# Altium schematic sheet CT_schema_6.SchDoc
size 251 x 159 mm
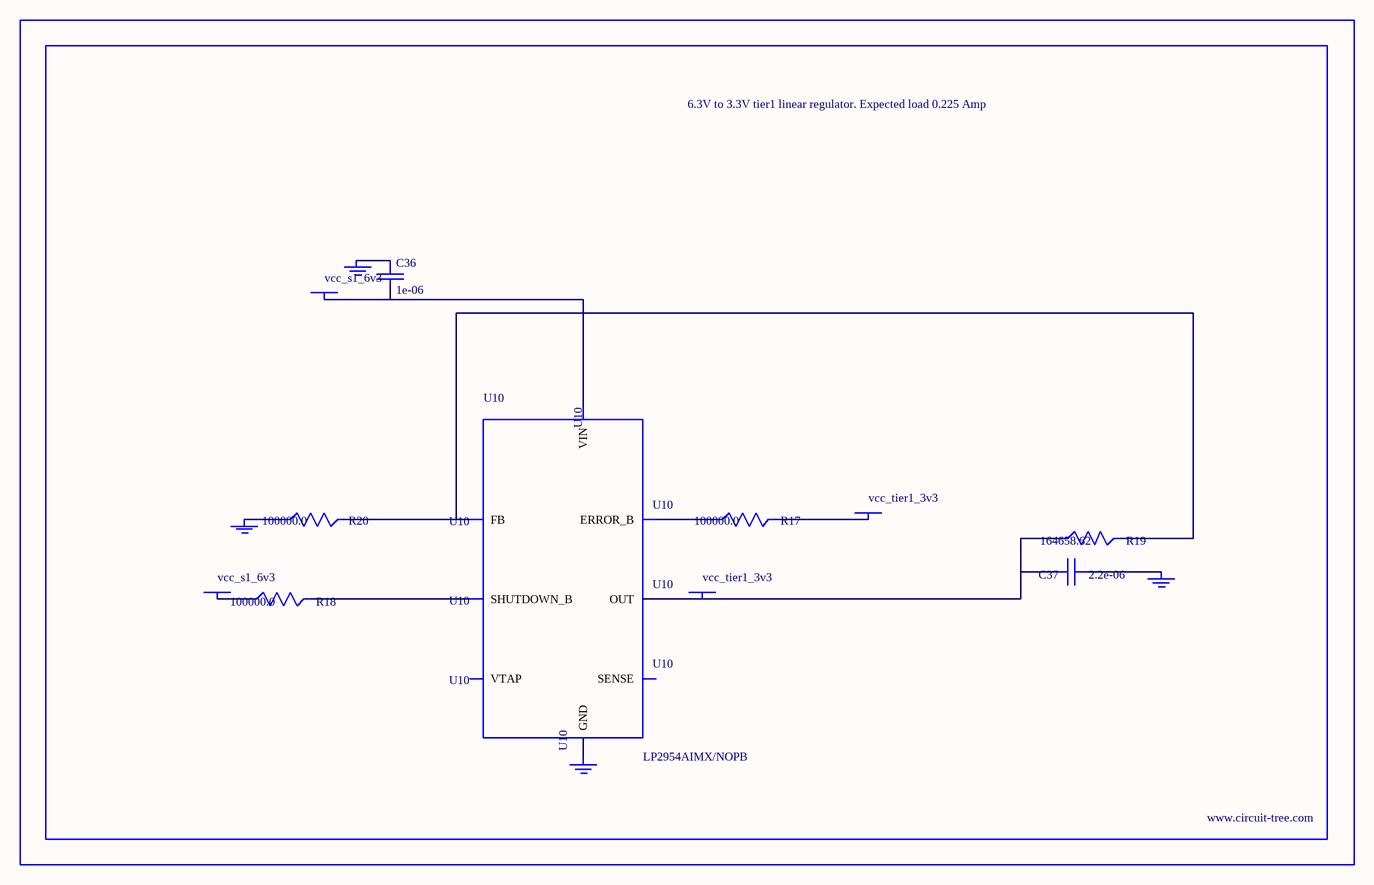
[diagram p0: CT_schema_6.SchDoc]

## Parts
BORDER5  (no value)
C36  1e-06  [EXV-9B]
C37  2.2e-06  [EXV-9B]
GND_INSTANCE_5_0  (no value)
GND_INSTANCE_5_1  (no value)
GND_INSTANCE_5_2  (no value)
GND_INSTANCE_5_3  (no value)
POWER_INSTANCE_5_0  vcc_s1_6v3
POWER_INSTANCE_5_1  vcc_tier1_3v3
POWER_INSTANCE_5_2  vcc_s1_6v3
POWER_INSTANCE_5_3  vcc_tier1_3v3
R17  100000.0  [R0603]
R18  100000.0  [R0603]
R19  164658.62  [R0603]
R20  100000.0  [R0603]
U10  LP2954AIMX/NOPB  [LP2954]

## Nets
NetC36_1: C36.1 GND_INSTANCE_5_2.0(GND)
NetC36_2: C36.2 POWER_INSTANCE_5_2.0(PWR) U10.8(VIN)
NetC37_1: C37.1 GND_INSTANCE_5_0.0(GND)
NetC37_2: C37.2 POWER_INSTANCE_5_3.0(PWR) R19.1 U10.1(OUT)
NetGND_INSTANCE_5_1_0: GND_INSTANCE_5_1.0(GND) R20.1
NetGND_INSTANCE_5_3_0: GND_INSTANCE_5_3.0(GND) U10.4(GND)
NetPOWER_INSTANCE_5_0_0: POWER_INSTANCE_5_0.0(PWR) R18.1
NetPOWER_INSTANCE_5_1_0: POWER_INSTANCE_5_1.0(PWR) R17.2
NetR17_1: R17.1 U10.5(ERROR_B)
NetR18_2: R18.2 U10.3(SHUTDOWN_B)
NetR19_2: R19.2 R20.2 U10.7(FB)

Not connected (* = marked no-connect by the designer): U10 2(SENSE) 6(VTAP)

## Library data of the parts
BORDER5 = BORDER_PAGE5
C36 = EDK105M050A9BAA
C37 = EDK225M050A9BAA
GND_INSTANCE_5_0-GND_INSTANCE_5_3 = GND
POWER_INSTANCE_5_0-POWER_INSTANCE_5_3 = PWR
R17 R18 R20 = RC0603JR-07100KL
R19 = R19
